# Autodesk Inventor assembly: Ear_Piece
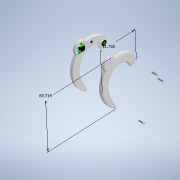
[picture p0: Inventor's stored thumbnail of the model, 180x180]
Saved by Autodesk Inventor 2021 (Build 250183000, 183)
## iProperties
Created: 2021-02
Part Number: Ear_Piece
Document SubType Name: Assembly
Designer: callu
Author: callu
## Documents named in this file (8)
- C:\Users\Meghan\Downloads\Ear_Piece (1).iam
- C:\Users\Meghan\Downloads\Battery.ipt
- C:\Users\Meghan\Downloads\BT_Chip.ipt
- C:\Users\Meghan\Downloads\EARPC_RS.ipt
- C:\Users\Meghan\Downloads\EARPC_LS.ipt
- C:\Users\Meghan\Downloads\Vibration_Motor.ipt
- C:\Users\Meghan\Downloads\Screw.ipt
- C:\Users\Meghan\Downloads\BMX160_Orentation_Sensor.ipt
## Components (9 placed, 7 different names)
1. Battery:1 — Mate:5, Mate:6, Mate:8, Mate:9, Mate:10
2. BT_Chip:1 — Mate:2, Mate:3, Mate:4
3. EARPC_RS:1 — Mate:2, Mate:3, Mate:4, Mate:7, Mate:8, Mate:9, Mate:10, Mate:13, Mate:14, Mate:15, Mate:16
4. EARPC_LS:1 — Mate:1, Mate:5, Mate:6, Mate:11, Mate:12, Mate:16, Mate:17, Flush:1, Flush:2, Flush:19
5. Vibration_Motor:1 — Mate:1, Mate:7
6. Screw:1 — Mate:11, Flush:2
7. Screw:2 — Mate:17, Flush:1
8. Screw:3 — Mate:12, Flush:19
9. BMX160_Orentation_Sensor:1 — Mate:13, Mate:14, Mate:15
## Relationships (20: Mate 17, Flush 3)
- Mate:1: EARPC_LS:1 ↔ Vibration_Motor:1
- Mate:2: BT_Chip:1 ↔ EARPC_RS:1
- Mate:3: BT_Chip:1 ↔ EARPC_RS:1
- Mate:4: BT_Chip:1 ↔ EARPC_RS:1
- Mate:5: Battery:1 ↔ EARPC_LS:1
- Mate:6: Battery:1 ↔ EARPC_LS:1
- Mate:7: EARPC_RS:1 ↔ Vibration_Motor:1
- Mate:8: Battery:1 ↔ EARPC_RS:1
- Mate:9: Battery:1 ↔ EARPC_RS:1
- Mate:10: Battery:1 ↔ EARPC_RS:1
- Mate:11: EARPC_LS:1 ↔ Screw:1
- Mate:12: EARPC_LS:1 ↔ Screw:3
- Mate:13: EARPC_RS:1 ↔ BMX160_Orentation_Sensor:1
- Mate:14: EARPC_RS:1 ↔ BMX160_Orentation_Sensor:1
- Mate:15: EARPC_RS:1 ↔ BMX160_Orentation_Sensor:1
- Mate:16: EARPC_RS:1 ↔ EARPC_LS:1
- Mate:17: EARPC_LS:1 ↔ Screw:2
- Flush:1: EARPC_LS:1 ↔ Screw:2
- Flush:2: EARPC_LS:1 ↔ Screw:1
- Flush:19: EARPC_LS:1 ↔ Screw:3
